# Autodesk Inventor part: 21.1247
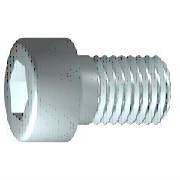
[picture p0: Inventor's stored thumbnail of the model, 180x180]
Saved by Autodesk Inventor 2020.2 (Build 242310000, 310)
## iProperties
Created: 2006-02
Part Number: 21.1247
Material: Steel, Mild
Description: M6 X 40 SHCS
Document SubType Name: Modeling
Standard: DIN 7984
Designer: Andy Moles
Standards Organization: DIN
Language: en-US
Size Designation: M6 x 40
Categories: <MemberInstance><Categories><Category DisplayName="Fasteners" InternalName="e4da775c-781d-43d5-af7c-5136215cf5a6" Mnemonic="FSTN"><Category DisplayName="Bolts"
Density: 7.85 g/cm^3
Mass: 10.9166 g
Surface Area: 10.6655 cm^2
Volume: 1.39065 cm^3
Appearance: Zinc
Author: Andy Moles
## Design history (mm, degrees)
sketch "Sketch1"
  geometry: L1 (0.333, 0)-(40, 0); L2 (40, 0)-(40, 3); L3 (40, 3)-(22, 3); L4 (22, 3)-(21.386, 3); L5 (21.386, 3)-(0, 3); L6 (0, 3)-(0, 5); L7 (0, 5)-(-4, 5); L8 (-4, 5)-(-4, 2.309); L9 (-4, 2.309)-(-1, 2.309); L10 (-1, 2.309)-(0.333, 0); L11 (-8.4, 0)-(53.2, 0) reference; L12 (0, -0.5)-(0, 6.5) reference; L13 (22, 3)-(0, 3)
  constraints: 22 end point, 6 parallel, 2 collinear, 2 perpendicular, 1 horizontal, 1 midpoint
  dimensions: "d1" = 18 distance from line of L3.end L2 (= GEL); "d2" = 0.61355 distance of L4.end L3.end (computed from GAL); "d3" = 4 distance between parallel lines of L8 L6 (= KOH); "d4" = 3 distance of L8.end L9.end (= INTI); "d5" = 60 deg angle of L10 L1; "d6" = 6 diameter of L3 L1 (= GD); "d7" = 6 diameter of L5 L1 (= BDM); "d8" = 4.6188 diameter of L9 L1 (= 1.1547 x SW); "d9" = 10 diameter of L7 L1 (= KOD); "d26" = 40 distance between parallel lines of L12 L2 (= NLG)
revolve "Body" sketch "Sketch1" stored, may be unused: angle "d10" = 90 deg
sketch "Sketch2"
  geometry: L1 (0, -6)-(0, 8) reference; L2 (-6, 0)-(8, 0) reference; L3 (2.309, 0)-(1.155, -2); L4 (1.155, -2)-(-1.155, -2); L5 (-1.155, -2)-(-2.309, 0); L6 (-2.309, 0)-(-1.155, 2); L7 (-1.155, 2)-(1.155, 2); L8 (1.155, 2)-(2.309, 0); 2 further points
  constraints: 12 end point, 1 coincident, 1 horizontal alignment, 1 point on line, 12 other
extrude "Slot" join sketch "Sketch2" stored distance "d11" = 10; taper "d12" = 0 deg
workplane "Work Plane1"
body "Solid1"
fillet "Fillet1" dims "d17" = 0.6 (= RR)
feature "Thread" dims "d13" = 18 (= GEL), "d14" = 0
chamfer "Chamfer1" distance "d15" = 0.61345 (= -0.5 x SPD + 0.5 x GD); stored, may be unused: second distance "d16" = 0.61345 (= GUL), angle "d27" = 45 deg
other parameters: "GD" = 6 (= NND) [user parameter; used in 2 equation terms], "NLG" = 40 [user parameter; used in 1 equation term], "GEL" = 18 [user parameter; used in 2 equation terms], "KOD" = 10 [user parameter; used in 1 equation term], "KOH" = 4 [user parameter; used in 1 equation term], "INTI" = 3 [user parameter; used in 1 equation term], "GAL" = 0.61345 (= 0.61345 x PTC) [user parameter; used in 1 equation term], "GUL" = 0.61345 (= 0.61345 x PTC) [user parameter; used in 1 equation term], "BDM" = 6 (= NND) [user parameter; used in 1 equation term], "SW" = 4 [user parameter; used in 2 equation terms], "RR" = 0.6 [user parameter; used in 1 equation term], "SPD" = 4.7731 (= NND - 1.2269 x PTC) [user parameter; used in 1 equation term], "d19" = 0, "d28" = 0, "d29" = 0, "TOA" = 30 deg [user parameter], "GD1" = 4.7731 (= THREADDIA - 1.2269 x PTC) [user parameter], "THREADDIA" = 6 [user parameter; used in 1 equation term], "FAWI" = 45 deg [user parameter], "ANG" = 120 deg [user parameter], "PTC" = 1 [user parameter; used in 5 equation terms], "NND" = 6 [user parameter; used in 3 equation terms], "E0" = 4.62 (= 1.155 x SW) [user parameter]
